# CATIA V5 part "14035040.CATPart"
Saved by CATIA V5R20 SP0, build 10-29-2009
Part number: 14035040
Definition: NONE
Nomenclature: 14035040
Source: Unknown
Description: 14035040
Bounding box of the stored display mesh (mm): x -20 to 80, y -31.5 to 21.6, z -21.6 to 21.6
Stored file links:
  C:\Users\Utente\Desktop\IO LAVORO\3D X SITO CF\X SITO\PLASTICA\RF2\14035040.CATPart
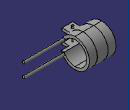
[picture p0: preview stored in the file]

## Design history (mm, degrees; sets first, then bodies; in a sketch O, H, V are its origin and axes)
Body1 "14035040" (main body)
  Solid1: solid without history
